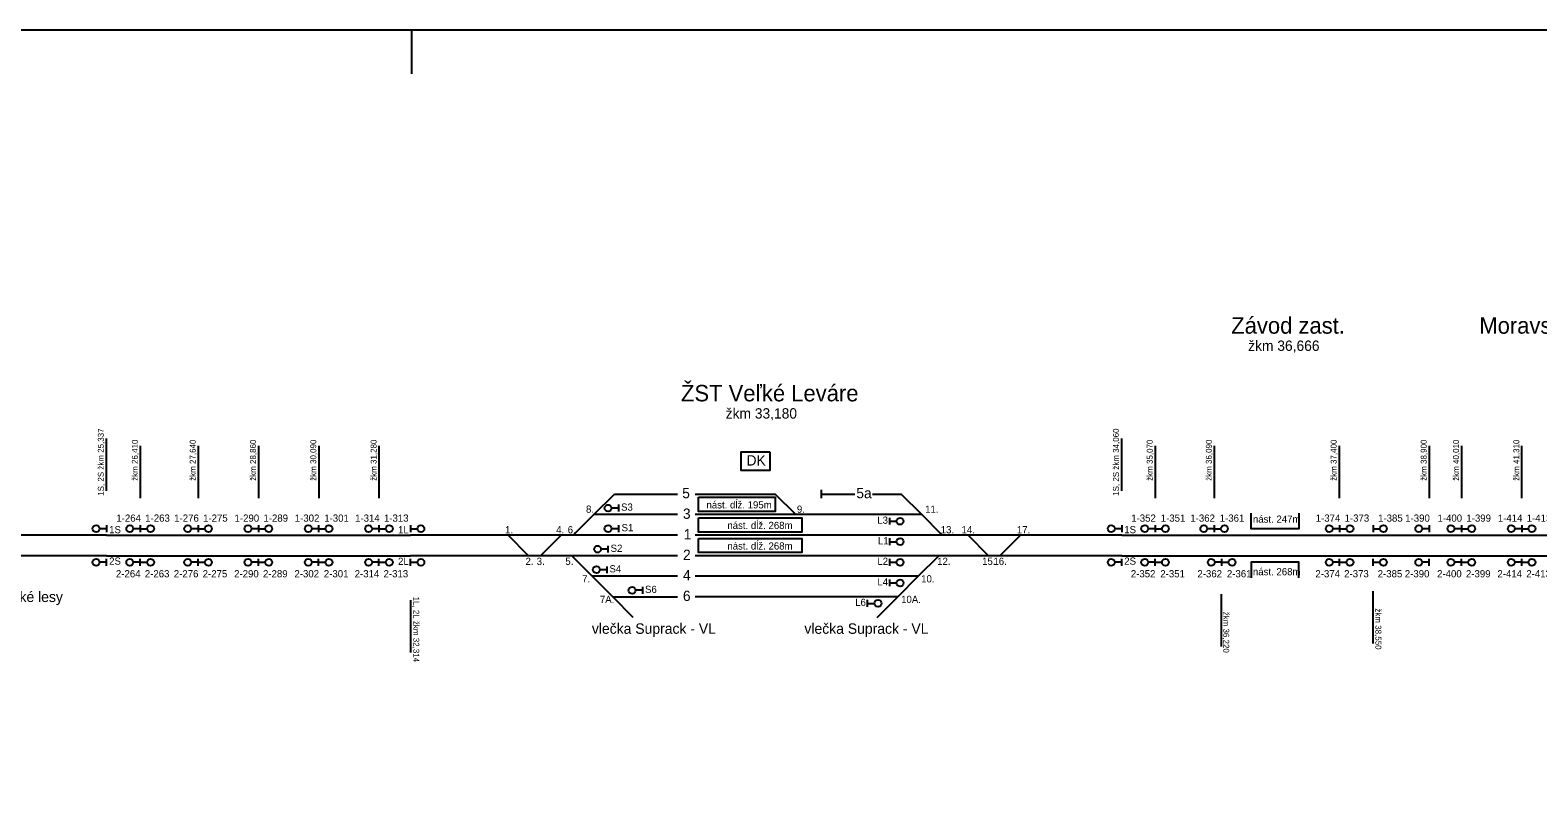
# Model space of a CAD drawing. Extents: x -119 to 851, y -238 to 59.
# Drawn here: x 243.9 to 390.6, y -15.3 to 59 of the extents above; entities that cross this region are included whole.
import ezdxf

# ---------------------------------------------------------------- set-up
doc = ezdxf.new("R2010")
doc.units = 0
for name, color, linetype in [('budova', 7, 'Continuous'), ('Level 2', 7, 'Continuous'), ('nastupistia', 7, 'Continuous'), ('netlač', 7, 'Continuous'), ('popisky navestidla', 7, 'Continuous'), ('popisky stanic a zastavok', 7, 'Continuous'), ('PU_navestidla', 7, 'Continuous'), ('PU_oznacenie navestidiel', 7, 'Continuous'), ('PU_stan_kolaje', 7, 'Continuous'), ('PU_vlecky', 7, 'Continuous')]:
    doc.layers.add(name, color=color, linetype=linetype)

msp = doc.modelspace()

# ---------------------------------------------------------------- linework, layer by layer
at = {"layer": 'budova'}
msp.add_lwpolyline([(315.95, 17.97), (313.08, 17.97), (313.08, 16.22), (315.95, 16.22)], close=True, dxfattribs=at)
at = {"layer": 'Level 2'}
for p, q in [((320.9, 14.29), (320.9, 13.49)), ((306.92, 11.89), (298.74, 11.89)), ((325.9, 11.89), (308.64, 11.89)), ((330.68, 11.89), (325.9, 11.89)), ((251.36, 9.89), (227.34, 9.89)), ((284.31, 9.89), (280.94, 9.89)), ((302.61, 9.89), (284.31, 9.89)), ((306.92, 9.89), (302.61, 9.89)), ((328.41, 9.89), (308.64, 9.89)), ((350.14, 9.89), (328.41, 9.89)), ((251.36, 7.89), (242.33, 7.89)), ((303.61, 7.89), (280.94, 7.89)), ((306.92, 7.89), (303.61, 7.89)), ((327.21, 7.89), (308.64, 7.89)), ((343.41, 7.89), (327.21, 7.89)), ((350.14, 7.89), (343.41, 7.89)), ((306.92, 5.89), (298.63, 5.89)), ((330.35, 5.89), (308.64, 5.89)), ((300.62, 3.89), (306.92, 3.89))]:
    msp.add_line(p, q, dxfattribs=at)
at = {"layer": 'nastupistia'}
for points in [[(308.98, 13.57), (316.44, 13.57), (316.44, 12.19), (308.98, 12.19)], [(308.98, 11.58), (319.02, 11.58), (319.02, 10.19), (308.98, 10.19)], [(308.98, 9.58), (319.02, 9.58), (319.02, 8.19), (308.98, 8.19)]]:
    msp.add_lwpolyline(points, close=True, dxfattribs=at)
for points in [[(367.37, 12.03), (367.37, 10.52), (362.73, 10.52), (362.73, 12.03)], [(367.37, 5.75), (367.37, 7.25), (362.73, 7.25), (362.73, 5.75)]]:
    msp.add_lwpolyline(points, dxfattribs=at)
at = {"layer": 'netlač'}
for p, q in [((300.78, 13.89), (306.92, 13.89)), ((308.64, 13.89), (316.43, 13.89)), ((320.9, 13.89), (324.18, 13.89)), ((325.9, 13.89), (328.69, 13.88)), ((251.36, 9.89), (280.94, 9.89)), ((350.14, 9.89), (403.92, 9.89)), ((251.36, 7.89), (280.94, 7.89)), ((350.14, 7.89), (403.92, 7.89)), ((328.35, 3.89), (308.64, 3.89))]:
    msp.add_line(p, q, dxfattribs=at)
at = {"layer": 'popisky navestidla'}
for p, q in [((281.05, 58.99), (281.05, 54.76)), ((251.36, 14.2), (251.36, 19.29)), ((350.14, 14.2), (350.14, 19.29)), ((254.67, 13.49), (254.67, 18.58)), ((260.31, 13.49), (260.31, 18.58)), ((266.17, 13.49), (266.17, 18.58)), ((272.04, 13.49), (272.04, 18.58)), ((277.9, 13.49), (277.9, 18.58)), ((353.43, 13.49), (353.43, 18.58)), ((359.17, 13.49), (359.17, 18.58)), ((371.32, 13.49), (371.32, 18.58)), ((380.09, 13.49), (380.09, 18.58)), ((383.23, 13.49), (383.23, 18.58)), ((389.09, 13.49), (389.09, 18.58)), ((374.57, 4.46), (374.57, -0.63)), ((280.94, 3.58), (280.94, -1.51)), ((359.83, 4.15), (359.83, -0.94))]:
    msp.add_line(p, q, dxfattribs=at)
msp.add_lwpolyline([(-118.95, -238.01), (851.05, -238.01), (851.05, 58.99), (-118.95, 58.99)], close=True, dxfattribs=at)
at = {"layer": 'PU_navestidla'}
for p, q in [((301.18, 12.52), (300.51, 12.52)), ((301.18, 12.86), (301.18, 12.19)), ((251.36, 10.52), (250.69, 10.52)), ((251.36, 10.86), (251.36, 10.19)), ((254.64, 10.52), (253.97, 10.52)), ((254.64, 10.86), (254.64, 10.19)), ((254.64, 10.86), (254.64, 10.19)), ((254.64, 10.52), (255.31, 10.52)), ((260.27, 10.52), (259.6, 10.52)), ((260.27, 10.86), (260.27, 10.19)), ((260.27, 10.86), (260.27, 10.19)), ((260.27, 10.52), (260.95, 10.52)), ((266.14, 10.52), (265.47, 10.52)), ((266.14, 10.86), (266.14, 10.19)), ((266.14, 10.86), (266.14, 10.19)), ((266.14, 10.52), (266.81, 10.52)), ((272, 10.52), (271.33, 10.52)), ((272, 10.86), (272, 10.19)), ((272, 10.86), (272, 10.19)), ((272, 10.52), (272.68, 10.52)), ((277.87, 10.52), (277.2, 10.52)), ((277.87, 10.86), (277.87, 10.19)), ((277.87, 10.86), (277.87, 10.19)), ((277.87, 10.52), (278.54, 10.52)), ((280.94, 10.86), (280.94, 10.19)), ((280.94, 10.52), (281.62, 10.52)), ((301.17, 10.52), (300.49, 10.52)), ((301.17, 10.86), (301.17, 10.19)), ((327.57, 10.92), (327.57, 11.59)), ((327.57, 11.25), (328.25, 11.25)), ((350.14, 10.52), (349.46, 10.52)), ((350.14, 10.86), (350.14, 10.19)), ((353.39, 10.52), (352.72, 10.52)), ((353.39, 10.86), (353.39, 10.19)), ((353.39, 10.86), (353.39, 10.19)), ((353.39, 10.52), (354.06, 10.52)), ((359.13, 10.52), (358.46, 10.52)), ((359.13, 10.86), (359.13, 10.19)), ((359.13, 10.86), (359.13, 10.19)), ((359.13, 10.52), (359.81, 10.52)), ((371.34, 10.52), (370.67, 10.52)), ((371.34, 10.86), (371.34, 10.19)), ((371.34, 10.86), (371.34, 10.19)), ((371.34, 10.52), (372.02, 10.52)), ((374.61, 10.86), (374.61, 10.19)), ((374.61, 10.52), (375.28, 10.52)), ((380.05, 10.52), (379.38, 10.52)), ((380.05, 10.86), (380.05, 10.19)), ((383.19, 10.52), (382.52, 10.52)), ((383.19, 10.86), (383.19, 10.19)), ((383.19, 10.86), (383.19, 10.19)), ((383.19, 10.52), (383.86, 10.52)), ((389.06, 10.52), (388.38, 10.52)), ((389.06, 10.86), (389.06, 10.19)), ((389.06, 10.86), (389.06, 10.19)), ((389.06, 10.52), (389.73, 10.52)), ((300.15, 8.86), (300.15, 8.19)), ((327.57, 8.92), (327.57, 9.59)), ((327.57, 9.25), (328.25, 9.25)), ((251.36, 6.92), (251.36, 7.59)), ((254.64, 6.92), (254.64, 7.59)), ((254.64, 6.92), (254.64, 7.59)), ((260.27, 6.92), (260.27, 7.59)), ((260.27, 6.92), (260.27, 7.59)), ((266.14, 6.92), (266.14, 7.59)), ((266.14, 6.92), (266.14, 7.59)), ((272, 6.92), (272, 7.59)), ((272, 6.92), (272, 7.59)), ((277.87, 6.92), (277.87, 7.59)), ((277.87, 6.92), (277.87, 7.59)), ((280.94, 6.92), (280.94, 7.59)), ((300.15, 8.52), (299.48, 8.52)), ((327.57, 6.92), (327.57, 7.59)), ((350.14, 6.92), (350.14, 7.59)), ((353.39, 6.92), (353.39, 7.59)), ((353.39, 6.92), (353.39, 7.59)), ((359.87, 6.92), (359.87, 7.59)), ((359.87, 6.92), (359.87, 7.59)), ((371.34, 6.92), (371.34, 7.59)), ((371.34, 6.92), (371.34, 7.59)), ((374.61, 6.92), (374.61, 7.59)), ((380.05, 6.92), (380.05, 7.59)), ((383.19, 6.92), (383.19, 7.59)), ((383.19, 6.92), (383.19, 7.59)), ((389.06, 6.92), (389.06, 7.59)), ((389.06, 6.92), (389.06, 7.59)), ((251.36, 7.25), (250.69, 7.25)), ((254.64, 7.25), (253.97, 7.25)), ((254.64, 7.25), (255.31, 7.25)), ((260.27, 7.25), (259.6, 7.25)), ((260.27, 7.25), (260.95, 7.25)), ((266.14, 7.25), (265.47, 7.25)), ((266.14, 7.25), (266.81, 7.25)), ((272, 7.25), (271.33, 7.25)), ((272, 7.25), (272.68, 7.25)), ((277.87, 7.25), (277.2, 7.25)), ((277.87, 7.25), (278.54, 7.25)), ((280.94, 7.25), (281.62, 7.25)), ((300.04, 6.53), (299.37, 6.53)), ((300.04, 6.86), (300.04, 6.19)), ((327.57, 7.25), (328.25, 7.25)), ((350.14, 7.25), (349.46, 7.25)), ((353.39, 7.25), (352.72, 7.25)), ((353.39, 7.25), (354.06, 7.25)), ((359.87, 7.25), (359.2, 7.25)), ((359.87, 7.25), (360.54, 7.25)), ((371.34, 7.25), (370.67, 7.25)), ((371.34, 7.25), (372.02, 7.25)), ((374.61, 7.25), (375.28, 7.25)), ((380.05, 7.25), (379.38, 7.25)), ((383.19, 7.25), (382.52, 7.25)), ((383.19, 7.25), (383.86, 7.25)), ((389.06, 7.25), (388.38, 7.25)), ((389.06, 7.25), (389.73, 7.25)), ((303.51, 4.53), (302.83, 4.53)), ((303.51, 4.86), (303.51, 4.19)), ((327.57, 4.92), (327.57, 5.59)), ((327.57, 5.26), (328.25, 5.26)), ((325.42, 2.92), (325.42, 3.59)), ((325.42, 3.26), (326.09, 3.26))]:
    msp.add_line(p, q, dxfattribs=at)
for centre in [(300.17, 12.52), (250.35, 10.53), (253.63, 10.52), (255.65, 10.52), (259.27, 10.52), (261.28, 10.52), (265.13, 10.52), (267.15, 10.52), (271, 10.52), (273.01, 10.52), (276.86, 10.52), (278.88, 10.52), (281.95, 10.52), (300.16, 10.52), (328.58, 11.25), (349.13, 10.53), (352.38, 10.52), (354.4, 10.52), (358.13, 10.52), (360.14, 10.52), (370.34, 10.52), (372.35, 10.52), (375.61, 10.52), (379.05, 10.52), (382.18, 10.52), (384.2, 10.52), (388.05, 10.52), (390.06, 10.52), (299.14, 8.53), (328.58, 9.25), (250.35, 7.25), (253.63, 7.25), (255.65, 7.25), (259.27, 7.25), (261.28, 7.25), (265.13, 7.25), (267.15, 7.25), (271, 7.25), (273.01, 7.25), (276.86, 7.25), (278.88, 7.25), (281.95, 7.25), (328.58, 7.25), (349.13, 7.25), (352.38, 7.25), (354.4, 7.25), (358.86, 7.25), (360.88, 7.25), (370.34, 7.25), (372.35, 7.25), (375.61, 7.25), (379.05, 7.25), (382.18, 7.25), (384.2, 7.25), (388.05, 7.25), (390.06, 7.25), (299.03, 6.53), (302.5, 4.53), (328.58, 5.25), (326.43, 3.26)]:
    msp.add_circle(centre, 0.336, dxfattribs=at)
at = {"layer": 'PU_stan_kolaje'}
for points in [[(298.78, 11.89), (300.78, 13.89)], [(318.43, 11.89), (316.44, 13.88)], [(330.68, 11.89), (328.69, 13.88)], [(296.78, 9.89), (298.78, 11.89)], [(332.68, 9.89), (330.69, 11.89)], [(292.43, 7.89), (290.43, 9.89)], [(293.6, 7.89), (295.6, 9.89)], [(337.19, 7.89), (335.19, 9.89)], [(338.28, 7.89), (340.28, 9.89)], [(298.63, 5.89), (296.63, 7.89)], [(330.35, 5.89), (332.35, 7.89)], [(300.62, 3.89), (298.63, 5.89)], [(328.35, 3.89), (330.35, 5.89)], [(302.62, 1.89), (300.62, 3.89)], [(326.35, 1.89), (328.35, 3.89)]]:
    msp.add_lwpolyline(points, dxfattribs=at)

# ---------------------------------------------------------------- texts
at = {"layer": 'budova'}
msp.add_text('DK', height=1.004, dxfattribs=at).set_placement((313.64, 16.66))
at = {"layer": 'nastupistia'}
for s, p in [('nást. dĺž. 195m', (309.74, 12.49)), ('nást. 247m', (362.91, 11.1)), ('nást. dĺž. 268m', (311.77, 10.49)), ('nást. dĺž. 268m', (311.77, 8.49)), ('nást. 268m', (362.91, 5.99))]:
    msp.add_text(s, height=0.7, dxfattribs=at).set_placement(p)
at = {"layer": 'popisky navestidla'}
for s, height, rotation, p in [('1S, 2S žkm 25,337', 0.5793, 90, (251.1, 13.72)), ('žkm 26,410', 0.579, 90, (254.41, 15.18)), ('žkm 27,640', 0.579, 90, (260.04, 15.18)), ('žkm 28,860', 0.579, 90, (265.91, 15.18)), ('žkm 30,090', 0.579, 90, (271.77, 15.18)), ('žkm 31,280', 0.579, 90, (277.64, 15.18)), ('1S, 2S žkm 34,060', 0.5793, 90, (349.87, 13.72)), ('žkm 35,070', 0.579, 90, (353.16, 15.18)), ('žkm 36,090', 0.579, 90, (358.91, 15.18)), ('žkm 37,400', 0.579, 90, (371.05, 15.18)), ('žkm 38,900', 0.579, 90, (379.82, 15.18)), ('žkm 40,010', 0.579, 90, (382.96, 15.18)), ('žkm 41,310', 0.579, 90, (388.83, 15.18)), ('1L, 2L žkm 32,314', 0.5793, 270, (281.21, 3.92)), ('žkm 36,220', 0.579, 270, (360.02, 2.45)), ('žkm 38,550', 0.579, 270, (374.83, 2.77))]:
    msp.add_text(s, height=height, rotation=rotation, dxfattribs=at).set_placement(p)
at = {"layer": 'popisky stanic a zastavok'}
for s, height, p in [('Závod zast.', 1.6, (360.8, 29.48)), ('Moravský Svätý Ján zast.', 1.6, (384.94, 29.48)), ('žkm 36,666', 1.004, (362.45, 27.81)), ('ŽST Veľké Leváre', 1.6, (307.26, 22.9)), ('žkm 33,180', 1.004, (311.61, 21.23))]:
    msp.add_text(s, height=height, dxfattribs=at).set_placement(p)
at = {"layer": 'PU_oznacenie navestidiel'}
for s, p in [('1-264', (252.32, 11.2)), ('1-263', (255.13, 11.2)), ('1-276', (257.95, 11.2)), ('1-275', (260.76, 11.2)), ('1-290', (263.82, 11.2)), ('1-289', (266.63, 11.2)), ('1-302', (269.68, 11.2)), ('1-301', (272.55, 11.2)), ('1-314', (275.55, 11.2)), ('1-313', (278.36, 11.2)), ('8.', (298.02, 12.07)), ('S3', (301.43, 12.27)), ('9.', (318.54, 12.07)), ('11.', (331.02, 12.07)), ('1-352', (351.07, 11.2)), ('1-351', (353.94, 11.2)), ('1-362', (356.82, 11.2)), ('1-361', (359.68, 11.2)), ('1-374', (369.02, 11.2)), ('1-373', (371.83, 11.2)), ('1-385', (375.09, 11.2)), ('1-390', (377.73, 11.2)), ('1-400', (380.87, 11.2)), ('1-399', (383.68, 11.2)), ('1-414', (386.74, 11.2)), ('1-413', (389.55, 11.2)), ('1S', (251.62, 10.08)), ('1L', (279.73, 10.07)), ('1.', (290.14, 10.07)), ('4.', (295.12, 10.07)), ('6.', (296.24, 10.07)), ('S1', (301.48, 10.27)), ('L3', (326.36, 11)), ('13.', (332.53, 10.07)), ('14.', (334.56, 10.07)), ('17.', (339.94, 10.07)), ('1S', (350.39, 10.08)), ('S2', (300.41, 8.27)), ('L1', (326.42, 9)), ('2S', (251.62, 7.02)), ('2L', (279.73, 7)), ('2.', (292.14, 7)), ('3.', (293.22, 7)), ('5.', (296.01, 7)), ('L2', (326.37, 7)), ('12.', (332.19, 7)), ('15.', (336.56, 7)), ('16.', (337.66, 7)), ('2S', (350.39, 7.02)), ('2-264', (252.28, 5.79)), ('2-263', (255.09, 5.79)), ('2-276', (257.91, 5.79)), ('2-275', (260.72, 5.79)), ('2-290', (263.78, 5.79)), ('2-289', (266.59, 5.79)), ('2-302', (269.65, 5.79)), ('2-301', (272.51, 5.79)), ('2-314', (275.51, 5.79)), ('2-313', (278.32, 5.79)), ('7.', (297.64, 5.3)), ('S4', (300.3, 6.27)), ('10.', (330.63, 5.3)), ('2-352', (351.03, 5.79)), ('2-351', (353.9, 5.79)), ('2-362', (357.51, 5.79)), ('2-361', (360.38, 5.79)), ('2-374', (368.99, 5.79)), ('2-373', (371.79, 5.79)), ('2-385', (375.05, 5.79)), ('2-390', (377.69, 5.79)), ('2-400', (380.83, 5.79)), ('2-399', (383.64, 5.79)), ('2-414', (386.7, 5.79)), ('2-413', (389.51, 5.79)), ('S6', (303.76, 4.27)), ('L4', (326.37, 5)), ('7A.', (299.37, 3.3)), ('L6', (324.21, 3.01)), ('10A.', (328.68, 3.3))]:
    msp.add_text(s, height=0.7, dxfattribs=at).set_placement(p)
at = {"layer": 'PU_stan_kolaje'}
for s, height, p in [('5', 1, (307.38, 13.48)), ('5a', 1.004, (324.32, 13.48)), ('3', 1, (307.45, 11.48)), ('1', 1, (307.53, 9.48)), ('2', 1, (307.46, 7.48)), ('4', 1, (307.45, 5.49)), ('6', 1, (307.45, 3.49))]:
    msp.add_text(s, height=height, dxfattribs=at).set_placement(p)
at = {"layer": 'PU_vlecky'}
for s, p in [('vlečka Vojenské lesy', (234.52, 3.39)), ('vlečka Suprack - VL', (298.59, 0.3)), ('vlečka Suprack - VL', (319.27, 0.3))]:
    msp.add_text(s, height=1.015, dxfattribs=at).set_placement(p)

doc.saveas('drawing.dxf')
